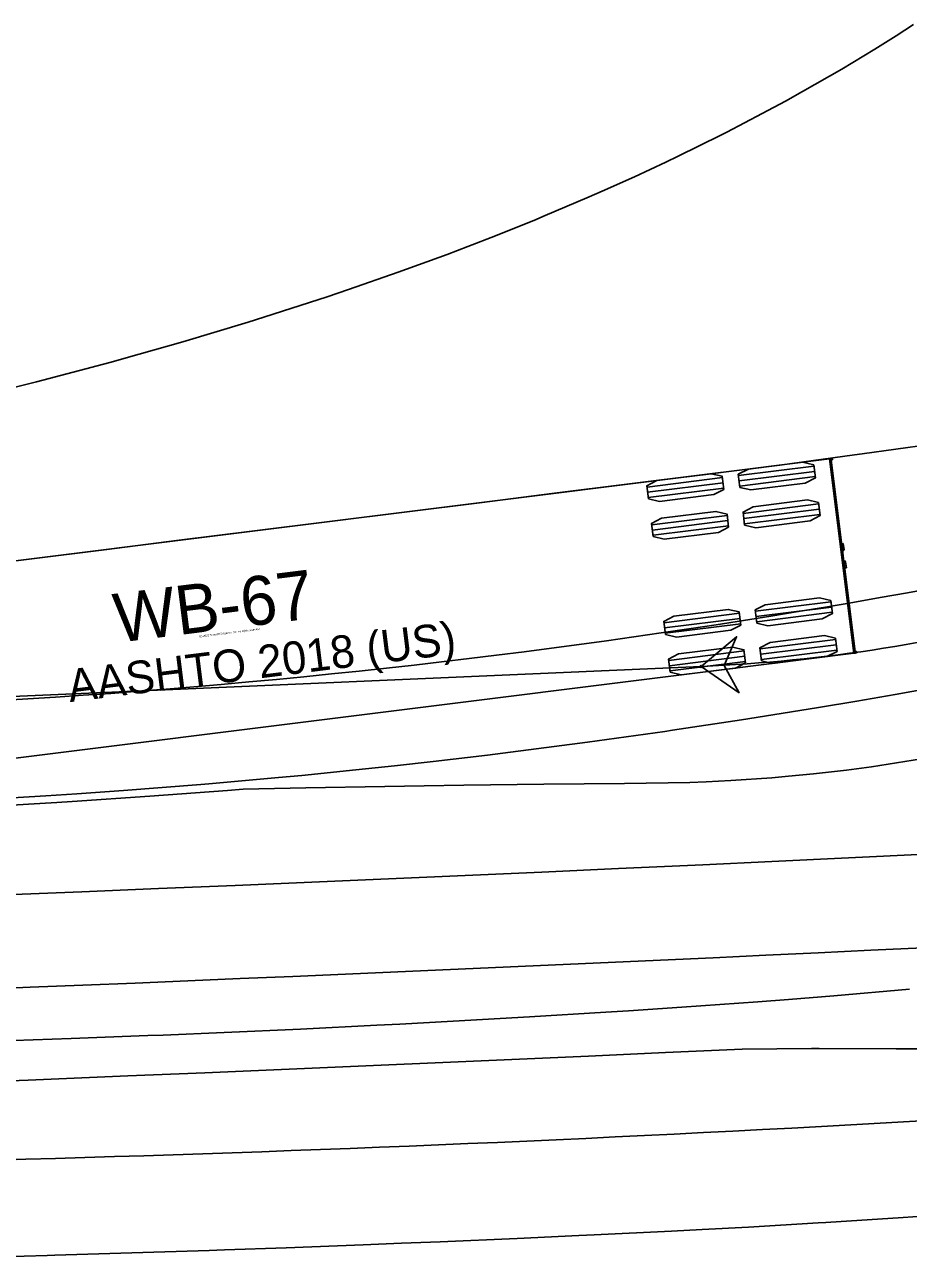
# Model space of a CAD drawing. Extents: x 973688 to 979179, y 703586 to 707602.
# Drawn here: x 977770.9 to 977809.3, y 704334.3 to 704387.8 of the extents above; entities that cross this region are included whole.
import ezdxf

# ---------------------------------------------------------------- set-up
doc = ezdxf.new("R2010")
doc.units = 0
for name, color, linetype in [('0-NPLT', 7, 'Continuous'), ('NB Left', 7, 'Continuous'), ('SB Left', 7, 'Continuous')]:
    doc.layers.add(name, color=color, linetype=linetype)

msp = doc.modelspace()

# ---------------------------------------------------------------- linework, layer by layer
at = {"layer": '0-NPLT'}
for points in [[(977770.076, 704350.051), (977773.404, 704350.185), (977773.737, 704350.199), (977776.732, 704350.322), (977780.059, 704350.461), (977783.387, 704350.603), (977786.715, 704350.746), (977787.047, 704350.761), (977790.042, 704350.892), (977793.369, 704351.04), (977796.696, 704351.191), (977800.023, 704351.344), (977800.356, 704351.359), (977803.35, 704351.499), (977806.677, 704351.656), (977810.002, 704351.816)], [(977805.401, 704343.386), (977805.067, 704343.386), (977802.063, 704343.361), (977798.73, 704343.207), (977795.397, 704343.055), (977792.065, 704342.906), (977788.732, 704342.758), (977786.399, 704342.657), (977785.399, 704342.613), (977782.066, 704342.471), (977778.733, 704342.33), (977775.399, 704342.192), (977772.066, 704342.056), (977771.066, 704342.016), (977768.733, 704341.923)], [(977810.414, 704343.37), (977808.743, 704343.367), (977805.401, 704343.386)]]:
    msp.add_lwpolyline(points, dxfattribs=at)
msp.add_arc((977575.914, 709194.827), 4852.716, 271.308632, 273.03356, dxfattribs=at)
at = {"layer": 'NB Left'}
for p, q in [((977805.851, 704368.971), (977800.228, 704368.268)), ((977801.902, 704368.246), (977805.176, 704368.656)), ((977805.921, 704368.98), (977805.851, 704368.971)), ((977805.851, 704368.972), (977806.907, 704360.537)), ((977805.924, 704368.958), (977805.921, 704368.98)), ((977805.927, 704368.933), (977805.927, 704368.934)), ((977806.378, 704365.326), (977805.927, 704368.933)), ((977800.228, 704368.268), (977753.401, 704362.408)), ((977797.933, 704367.75), (977801.207, 704368.16)), ((977801.93, 704368.019), (977805.205, 704368.429)), ((977801.959, 704367.792), (977805.233, 704368.201)), ((977797.961, 704367.522), (977801.236, 704367.932)), ((977797.99, 704367.295), (977801.264, 704367.705)), ((977802.107, 704366.609), (977805.381, 704367.019)), ((977798.138, 704366.113), (977801.412, 704366.522)), ((977802.135, 704366.382), (977805.41, 704366.792)), ((977802.164, 704366.154), (977805.438, 704366.564)), ((977798.166, 704365.885), (977801.44, 704366.295)), ((977798.194, 704365.658), (977801.469, 704366.068)), ((977806.383, 704365.29), (977806.378, 704365.326)), ((977806.452, 704365.299), (977806.383, 704365.29)), ((977806.383, 704365.29), (977806.416, 704365.027)), ((977806.481, 704364.507), (977806.416, 704365.024)), ((977806.453, 704365.298), (977806.452, 704365.299)), ((977806.486, 704365.033), (977806.453, 704365.298)), ((977806.449, 704364.763), (977806.379, 704364.755)), ((977806.482, 704364.5), (977806.515, 704364.236)), ((977806.585, 704364.246), (977806.551, 704364.511)), ((977806.515, 704364.236), (977806.584, 704364.245)), ((977806.519, 704364.201), (977806.515, 704364.236)), ((977806.971, 704360.593), (977806.519, 704364.201)), ((977806.584, 704364.245), (977806.585, 704364.246)), ((977802.639, 704362.359), (977805.913, 704362.769)), ((977798.669, 704361.862), (977801.944, 704362.272)), ((977802.667, 704362.132), (977805.941, 704362.541)), ((977802.695, 704361.904), (977805.97, 704362.314)), ((977798.698, 704361.635), (977801.972, 704362.045)), ((977798.726, 704361.408), (977802.001, 704361.817)), ((977802.843, 704360.722), (977806.118, 704361.132)), ((977798.874, 704360.225), (977802.149, 704360.635)), ((977802.872, 704360.494), (977806.146, 704360.904)), ((977802.9, 704360.267), (977806.175, 704360.677)), ((977806.971, 704360.592), (977806.971, 704360.593)), ((977806.977, 704360.547), (977806.974, 704360.568)), ((977798.903, 704359.998), (977802.177, 704360.408)), ((977798.931, 704359.77), (977802.206, 704360.18)), ((977801.283, 704359.834), (977806.906, 704360.538)), ((977806.906, 704360.538), (977806.977, 704360.547)), ((977754.457, 704353.974), (977801.283, 704359.834))]:
    msp.add_line(p, q, dxfattribs=at)
for points in [[(977767.845, 704364.215), (977771.111, 704364.624), (977774.373, 704365.032), (977777.632, 704365.44), (977780.889, 704365.848), (977784.146, 704366.255), (977787.402, 704366.663), (977790.659, 704367.07), (977793.917, 704367.478), (977797.177, 704367.886), (977800.435, 704368.294), (977802.064, 704368.498), (977803.692, 704368.706), (977806.943, 704369.141), (977807.268, 704369.186), (977810.192, 704369.6)], [(977811.036, 704359.172), (977808.707, 704358.752), (977807.041, 704358.463), (977805.374, 704358.182), (977803.039, 704357.803), (977802.038, 704357.646), (977799.034, 704357.193), (977798.7, 704357.144), (977795.357, 704356.676), (977795.023, 704356.631), (977792.01, 704356.242), (977791.004, 704356.118), (977788.657, 704355.841), (977786.979, 704355.653), (977785.299, 704355.474), (977782.946, 704355.237), (977781.937, 704355.14), (977778.909, 704354.869), (977778.572, 704354.841), (977775.203, 704354.575), (977773.181, 704354.432), (977771.833, 704354.343), (977768.46, 704354.146)]]:
    msp.add_lwpolyline(points, dxfattribs=at)
for points in [[(977801.966, 704367.735), (977801.895, 704368.303), (977802.332, 704368.531), (977804.689, 704368.826), (977805.169, 704368.713), (977805.24, 704368.145), (977804.803, 704367.917), (977802.446, 704367.622)], [(977797.997, 704367.239), (977797.926, 704367.806), (977798.363, 704368.035), (977800.72, 704368.33), (977801.2, 704368.216), (977801.271, 704367.648), (977800.834, 704367.42), (977798.476, 704367.125)], [(977802.171, 704366.098), (977802.1, 704366.666), (977802.537, 704366.894), (977804.894, 704367.189), (977805.374, 704367.075), (977805.445, 704366.508), (977805.008, 704366.279), (977802.65, 704365.984)], [(977798.202, 704365.601), (977798.131, 704366.169), (977798.568, 704366.397), (977800.925, 704366.692), (977801.405, 704366.579), (977801.476, 704366.011), (977801.039, 704365.783), (977798.681, 704365.488)], [(977802.702, 704361.848), (977802.631, 704362.415), (977803.068, 704362.644), (977805.426, 704362.939), (977805.906, 704362.825), (977805.977, 704362.258), (977805.54, 704362.029), (977803.182, 704361.734)], [(977798.733, 704361.351), (977798.662, 704361.919), (977799.099, 704362.147), (977801.457, 704362.442), (977801.937, 704362.329), (977802.008, 704361.761), (977801.571, 704361.533), (977799.213, 704361.238)], [(977802.907, 704360.211), (977802.836, 704360.778), (977803.273, 704361.007), (977805.631, 704361.302), (977806.111, 704361.188), (977806.182, 704360.62), (977805.745, 704360.392), (977803.387, 704360.097)], [(977798.938, 704359.714), (977798.867, 704360.282), (977799.304, 704360.51), (977801.662, 704360.805), (977802.142, 704360.691), (977802.213, 704360.124), (977801.776, 704359.895), (977799.418, 704359.6)]]:
    msp.add_lwpolyline(points, close=True, dxfattribs=at)
for centre in [(977805.959, 704368.951), (977807.006, 704360.584)]:
    msp.add_circle(centre, 0.0266, dxfattribs=at)
for centre, radius, start, end in [((977807.93, 704369.209), 2.022, 187.1332, 187.817), ((977806.451, 704365.029), 0.0354, 11.4248, 183.6102), ((977806.451, 704365.029), 0.0352, 188.1076, 7.108), ((977806.517, 704364.507), 0.0352, 7.1585, 186.1589), ((977806.517, 704364.506), 0.0353, 190.4694, 8.8191), ((977750.53, 704689.039), 331.122, 267.7291, 281.0455), ((977807.006, 704360.584), 0.0363, 206.2107, 167.372)]:
    msp.add_arc(centre, radius, start, end, dxfattribs=at)
at = {"layer": 'SB Left'}
msp.add_line((977800.288, 704359.966), (977662.142, 704353.954), dxfattribs=at)
for points in [[(977768.22, 704371.523), (977771.428, 704372.318), (977774.619, 704373.161), (977775.89, 704373.513), (977777.789, 704374.055), (977780.622, 704374.905), (977780.935, 704375.002), (977784.051, 704376.006), (977784.98, 704376.319), (977787.131, 704377.069), (977789.259, 704377.847), (977790.161, 704378.189), (977791.354, 704378.653), (977793.12, 704379.364), (977793.412, 704379.484), (977795.423, 704380.338), (977795.989, 704380.586), (977797.384, 704381.214), (977798.751, 704381.851), (977799.289, 704382.108), (977801.138, 704383.02), (977801.398, 704383.153), (977802.936, 704383.954), (977803.941, 704384.497), (977804.685, 704384.909), (977806.391, 704385.889), (977807.819, 704386.75), (977808.752, 704387.335), (977809.501, 704387.817)], [(977800.288, 704359.966), (977801.927, 704358.82), (977801.287, 704360.01), (977801.819, 704361.253), (977800.288, 704359.966)], [(977809.85, 704355.948), (977808.404, 704355.717), (977807.681, 704355.613), (977806.597, 704355.47), (977805.155, 704355.304), (977804.076, 704355.198), (977803.358, 704355.137), (977801.568, 704355.014), (977800.498, 704354.961), (977799.786, 704354.934), (977796.95, 704354.889), (977793.448, 704354.856), (977789.985, 704354.814), (977788.264, 704354.788), (977786.548, 704354.761), (977783.13, 704354.697), (977780.405, 704354.637), (977779.73, 704354.584), (977776.355, 704354.335), (977772.984, 704354.109), (977772.31, 704354.066), (977769.617, 704353.901)], [(977769.627, 704343.707), (977772.945, 704343.818), (977776.262, 704343.942), (977776.926, 704343.968), (977779.579, 704344.078), (977782.894, 704344.228), (977786.209, 704344.39), (977787.204, 704344.441), (977789.523, 704344.566), (977792.835, 704344.755), (977796.144, 704344.959), (977797.136, 704345.023), (977799.449, 704345.177), (977802.75, 704345.412), (977804.069, 704345.511), (977806.045, 704345.668), (977809.333, 704345.953)], [(977812.402, 704336.284), (977809.046, 704336.049), (977805.692, 704335.833), (977805.357, 704335.812), (977802.341, 704335.635), (977800.331, 704335.525), (977798.991, 704335.456), (977795.644, 704335.294), (977794.975, 704335.263), (977792.299, 704335.142), (977788.954, 704334.999), (977787.282, 704334.931), (977785.61, 704334.865), (977782.266, 704334.739), (977779.591, 704334.644), (977778.922, 704334.622), (977775.578, 704334.513), (977772.234, 704334.412), (977771.899, 704334.403), (977768.889, 704334.321)]]:
    msp.add_lwpolyline(points, dxfattribs=at)
msp.add_lwpolyline([(977800.288, 704359.966), (977801.927, 704358.82), (977801.287, 704360.01), (977801.819, 704361.253)], close=True, dxfattribs=at)
msp.add_circle((977800.288, 704359.966), 0.0417, dxfattribs=at)
msp.add_circle((977800.288, 704359.966), 0.0417, dxfattribs=at)
for centre, radius, start, end in [((977797.34, 704429.822), 69.919, 272.4166, 285.4473), ((977734.132, 705652.213), 1314.152, 266.306669, 273.447933)]:
    msp.add_arc(centre, radius, start, end, dxfattribs=at)

# ---------------------------------------------------------------- texts
at = {"layer": 'NB Left'}
for s, height, p in [('WB-67', 2.125, (977774.932, 704360.99)), ('AASHTO 2018 (US)', 1.41667, (977772.883, 704358.414)), ('(c) 2022 Transoft Solutions, Inc. All rights reserved.', 0.085, (977778.502, 704361.223))]:
    msp.add_text(s, height=height, rotation=7.1332, dxfattribs=at).set_placement(p)

doc.saveas('drawing.dxf')
